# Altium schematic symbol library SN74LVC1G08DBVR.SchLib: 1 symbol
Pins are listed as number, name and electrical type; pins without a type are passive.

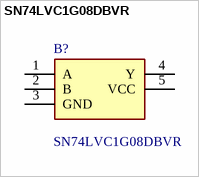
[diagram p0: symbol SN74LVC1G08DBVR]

## SN74LVC1G08DBVR
designator B?
SN74LVC1G08 Single 2-Input Positive-AND Gate; Manufacturer_Name: Texas Instruments; Geometry.Height: 1.45mm
footprint SOT95P280X145-5N
pins: 1 A, 2 B, 3 GND, 4 Y, 5 VCC (power)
